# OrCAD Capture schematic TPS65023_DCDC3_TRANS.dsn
size Custom; title: TPS65023x Power Management IC (PMIC) With 3 DC/DCs,; rev: 1.0; note: Datasheet: SLVS670L     EVM: SLVU193; note: Synchronous Step Down Converter
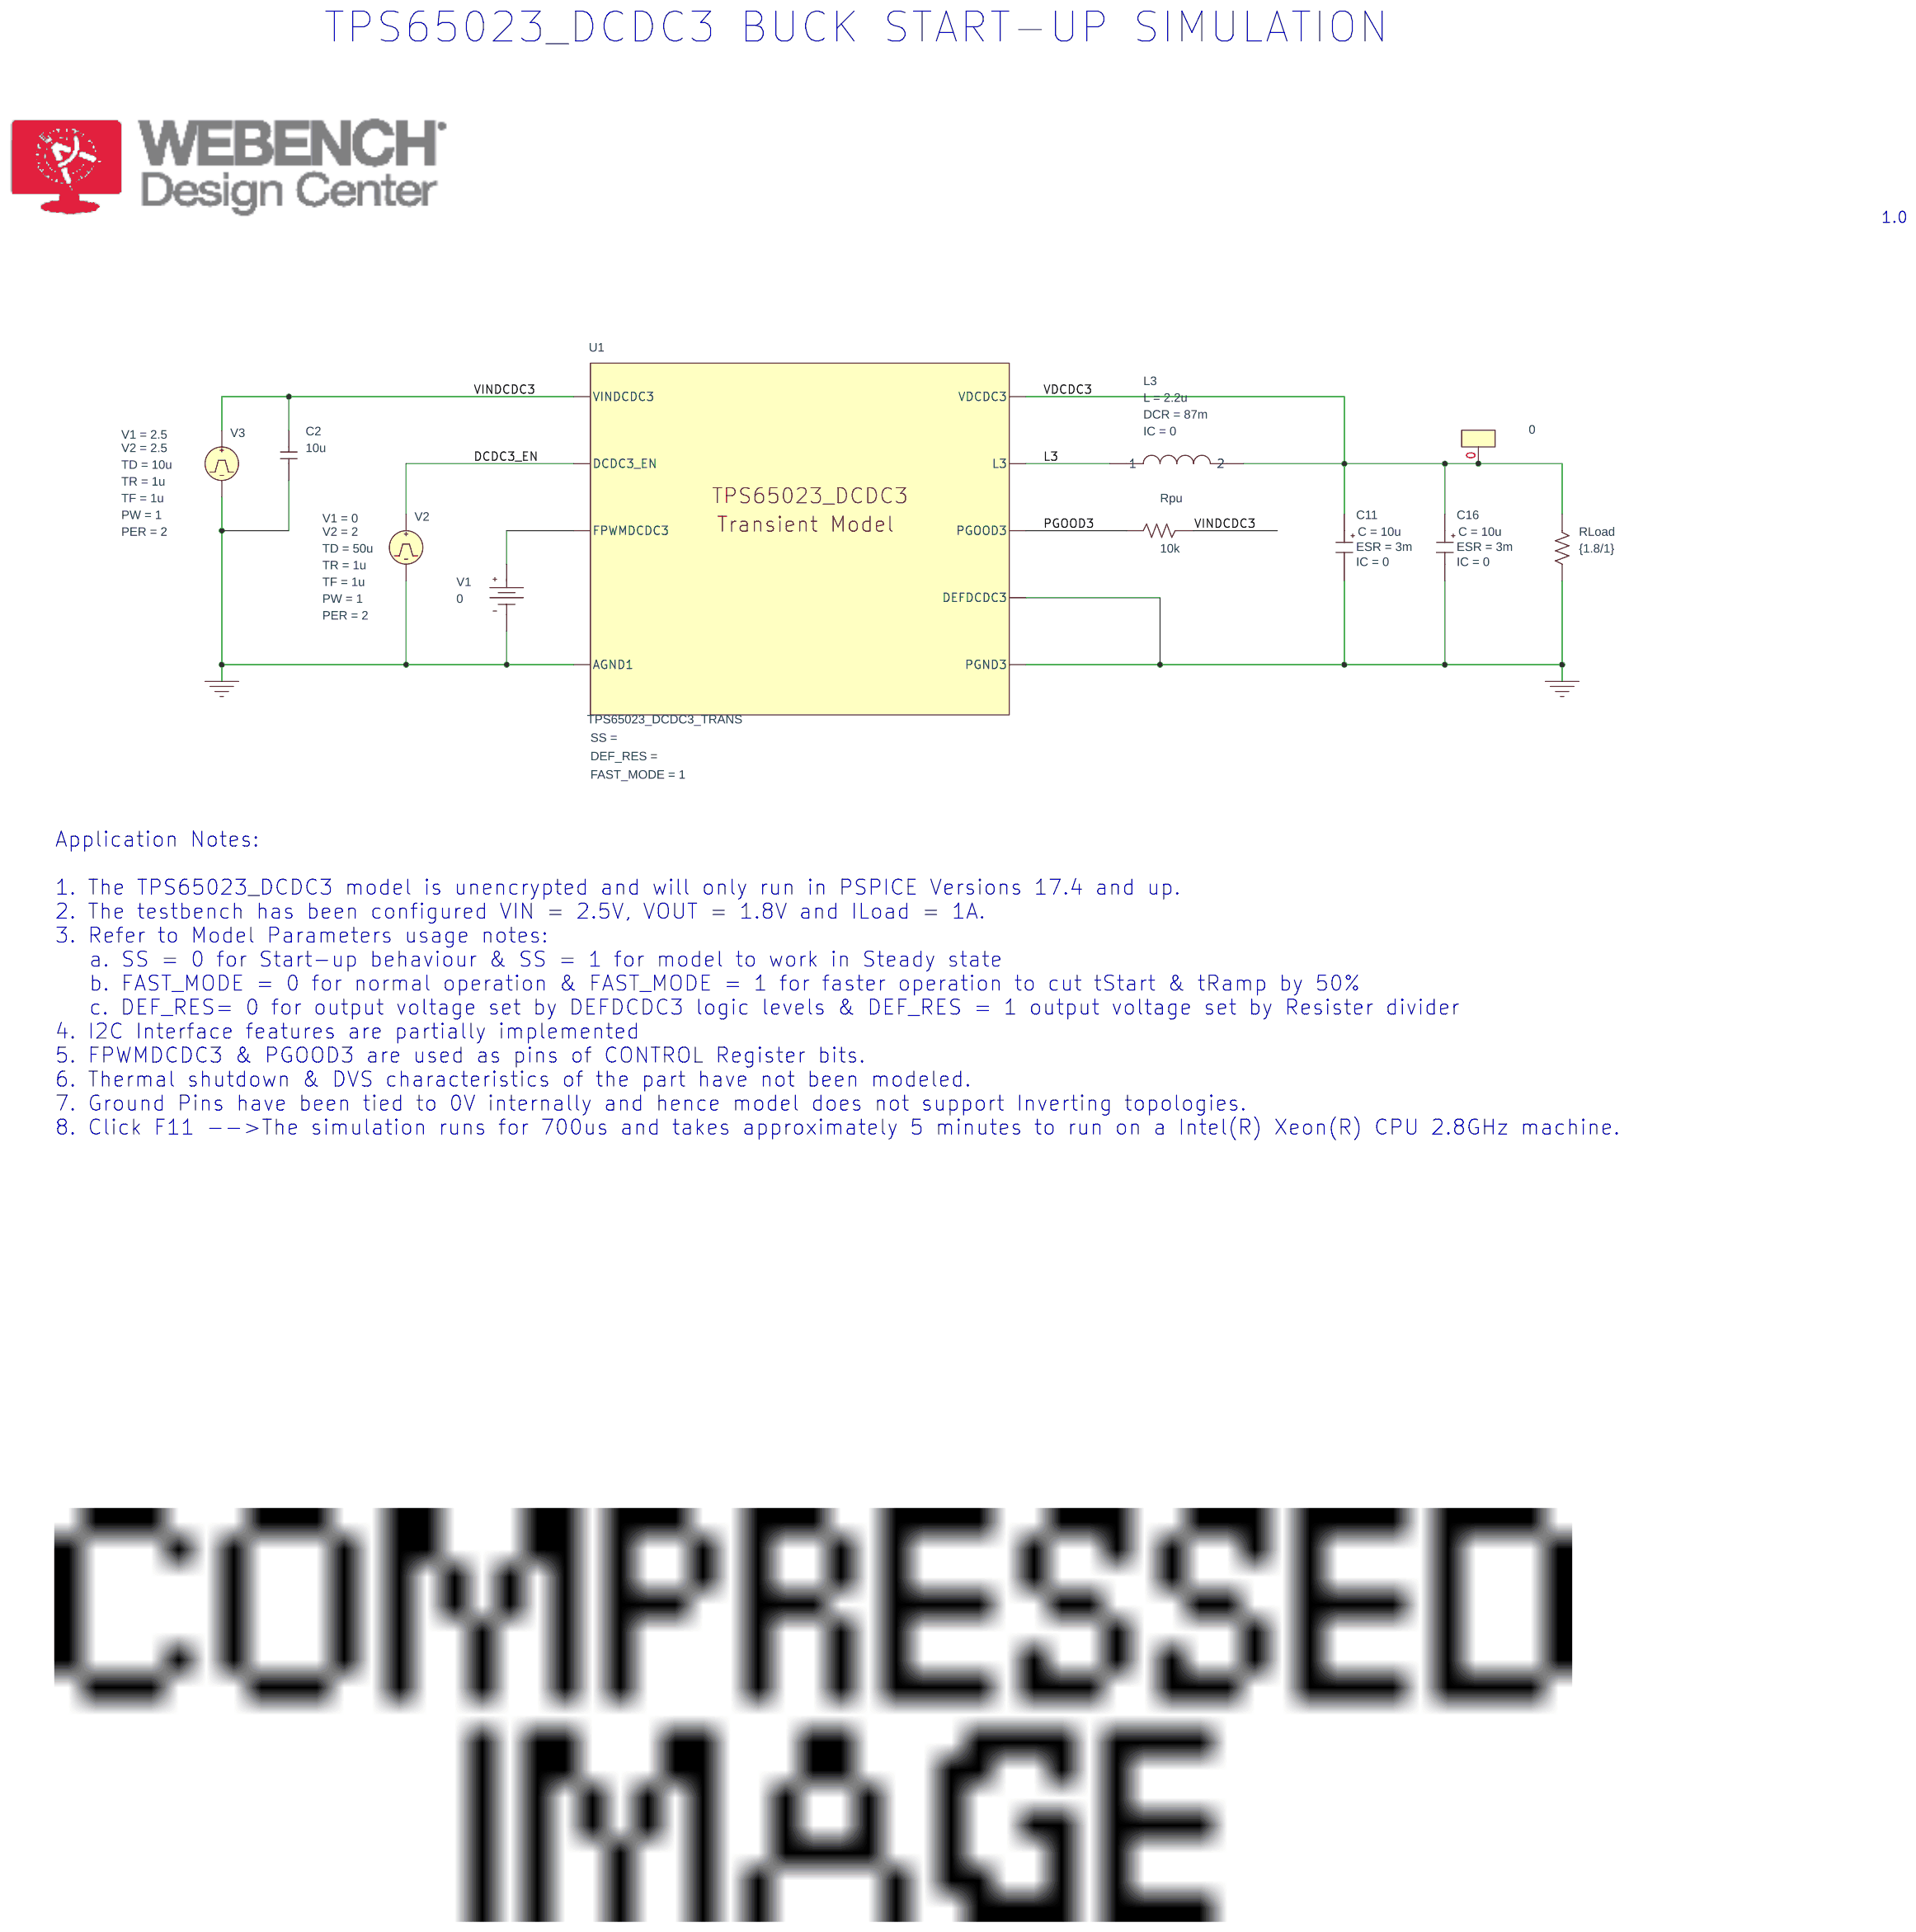
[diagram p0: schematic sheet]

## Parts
C2  10u  [RAD/CK05]
C11  CESR
C16  CESR
IC2  0
L3  LDCR
RLoad  {1.8/1}  [AX/RC05]
Rpu  10k  [AX/RC05]
U1  TPS65023_DCDC3_TRANS
V1  VDC
V2  VPULSE
V3  VPULSE

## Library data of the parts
C2 = C
C11 C16 = CESR_0: C: 10u; ESR: 3m; IC: 0; PSpiceTemplate: X^@REFDES %IN %OUT @MODEL PARAMS:  ?C|C=@C||C=100u|  ?ESR|ESR=@ESR||ESR=0.01| ?X|X=@X||X=2|  ?IC|IC=@IC||IC=2|; X: 1
IC2 = IC1
L3 = LDCR: DCR: 87m; IC: 0; L: 2.2u
RLoad Rpu = R
U1 = TPS65023_DCDC3_TRANS: FAST_MODE: 1
V1 = VDC: DC: 0
V2 = VPULSE: PER: 2; PW: 1; TD: 50u; TF: 1u; TR: 1u; V1: 0; V2: 2
V3 = VPULSE: PER: 2; PW: 1; TD: 10u; TF: 1u; TR: 1u; V1: 2.5; V2: 2.5

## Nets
VINDCDC3: C2.1 Rpu.1 U1.VINDCDC3 V3.1(+)
0: C2.2 C11.2(OUT) C16.2(OUT) RLoad.2 U1.AGND1 U1.DEFDCDC3 U1.PGND3 V1.1(-) V2.2(-) V3.2(-)
DCDC3_EN: U1.DCDC3_EN V2.1(+)
L3: L3.1 U1.L3
PGOOD3: Rpu.2 U1.PGOOD3
VDCDC3: C11.1(IN) C16.1(IN) IC2.0(+) L3.2 RLoad.1 U1.VDCDC3
N16777962: U1.FPWMDCDC3 V1.0(+)

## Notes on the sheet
- TPS65023_DCDC3 BUCK START-UP SIMULATION
- 1.0
- Application Notes:
  1. The TPS65023_DCDC3 model is unencrypted and will only run in PSPICE Versions 17.4 and up.
  2. The testbench has been configured VIN = 2.5V, VOUT = 1.8V and ILoad = 1A.
  3. Refer to Model Parameters usage notes:
     a. SS = 0 for Start-up behaviour & SS = 1 for model to work in Steady state
     b. FAST_MODE = 0 for normal operation & FAST_MODE = 1 for faster operation to cut tStart & tRamp by 50%
     c. DEF_RES= 0 for output voltage set by DEFDCDC3 logic levels & DEF_RES = 1 output voltage set by Resister divider
  4. I2C Interface features are partially implemented
  5. FPWMDCDC3 & PGOOD3 are used as pins of CONTROL Register bits.
  6. Thermal shutdown & DVS characteristics of the part have not been modeled.
  7. Ground Pins have been tied to 0V internally and hence model does not support Inverting topologies.
  8. Click F11 -->The simulation runs for 700us and takes approximately 5 minutes to run on a Intel(R) Xeon(R) CPU 2.8GHz machine.
